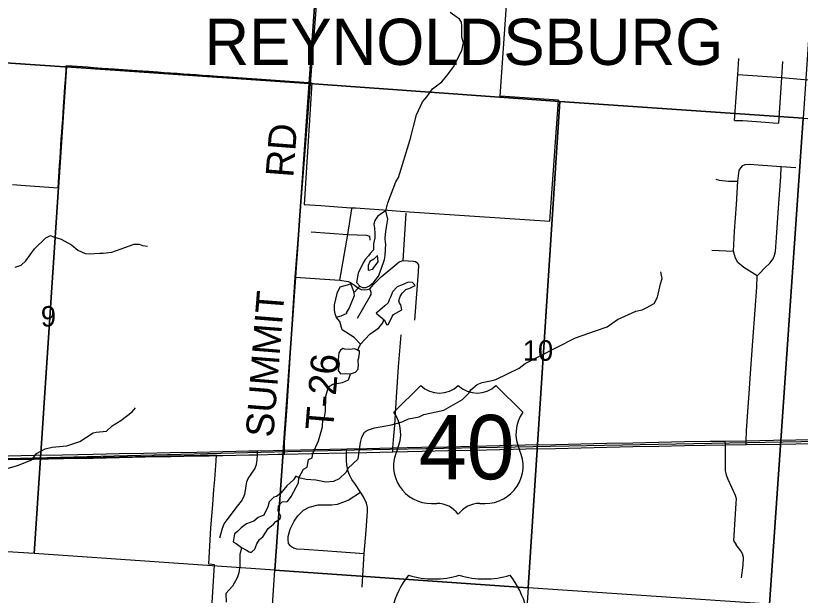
# Model space of a CAD drawing. Extents: x 0 to 34, y 0 to 22.
# Drawn here: x 4.853 to 6.46, y 19.099 to 20.286 of the extents above; entities that cross this region are included whole.
import ezdxf

# ---------------------------------------------------------------- set-up
doc = ezdxf.new("R2010")
doc.units = 0
for name, color, linetype in [('GM_X_Corporation', 7, 'Continuous'), ('GM_X_Corporation_Text', 7, 'Continuous'), ('GM_X_Interstate_Shield', 7, 'Continuous'), ('GM_X_Minor_Lake', 7, 'Continuous'), ('GM_X_Minor_River', 7, 'Continuous'), ('GM_X_Rail_Line', 7, 'Continuous'), ('GM_X_Section_Text', 7, 'Continuous'), ('GM_X_Township_Road', 7, 'Continuous'), ('GM_X_Township_Road_Text', 7, 'Continuous'), ('GM_X_US_Location', 7, 'Continuous'), ('GM_X_US_Route', 7, 'Continuous'), ('GM_X_US_Shield', 7, 'Continuous')]:
    doc.layers.add(name, color=color, linetype=linetype)

msp = doc.modelspace()

# ---------------------------------------------------------------- linework, layer by layer
at = {"layer": 'GM_X_Corporation'}
for points in [[(4.4912, 20.7461), (4.8271, 20.7263), (5.3592, 20.6938), (5.4919, 20.6855), (5.4537, 20.1473), (4.9568, 20.181), (4.9537, 20.1812), (4.4572, 20.2143)], [(5.4919, 20.6855), (5.8824, 20.6656), (6.3999, 20.6351), (6.5029, 20.629), (6.4654, 20.076), (5.9674, 20.1102), (5.4537, 20.1473)], [(4.4572, 20.2143), (4.9537, 20.1812), (4.9568, 20.181), (4.8908, 19.1842), (4.3886, 19.2156)], [(4.9568, 20.181), (5.4537, 20.1473), (5.3836, 19.1504), (4.8908, 19.1842)], [(5.4537, 20.1473), (5.9674, 20.1102), (5.9022, 19.114), (5.3836, 19.1504)], [(5.9674, 20.1102), (6.4654, 20.076), (6.3967, 19.0805), (5.9022, 19.114)], [(6.4654, 20.076), (6.9844, 20.0383), (6.914, 19.0437), (6.3967, 19.0805)], [(5.3836, 19.1504), (5.9022, 19.114), (5.8356, 18.116), (5.3174, 18.1535)]]:
    msp.add_lwpolyline(points, close=True, dxfattribs=at)
for points in [[(4.8462, 19.9402), (4.8724, 19.9383), (4.8824, 19.9376), (4.9399, 19.9335), (4.9427, 19.9787), (4.9438, 19.9938), (4.9447, 20.0075), (4.9456, 20.0201), (4.9465, 20.0336), (4.9474, 20.0467), (4.9483, 20.0599), (4.9493, 20.0734), (4.9502, 20.0864), (4.9511, 20.1), (4.9523, 20.1177), (4.9539, 20.1402), (4.9549, 20.1545), (4.9569, 20.1838), (4.9689, 20.1829), (4.9998, 20.1808), (5.0132, 20.1799), (5.0304, 20.1787), (5.0547, 20.1769), (5.0817, 20.1752), (5.1017, 20.1738), (5.1259, 20.172), (5.1438, 20.1708), (5.1572, 20.1698), (5.1703, 20.1689), (5.1835, 20.1679), (5.1969, 20.167), (5.2103, 20.166), (5.2227, 20.1651), (5.2359, 20.1642), (5.2497, 20.1632), (5.2662, 20.162), (5.2897, 20.1604), (5.3079, 20.1591), (5.4529, 20.1488), (5.4597, 20.1483), (5.4437, 19.8991), (5.4777, 19.8968), (5.5393, 19.8924), (5.5488, 19.892), (5.606, 19.8881), (5.6501, 19.8851), (5.6596, 19.8841), (5.6901, 19.8824), (5.947, 19.865), (5.9645, 20.1129), (5.8451, 20.1209), (5.864, 20.3961)], [(5.2534, 19.0508), (5.2599, 19.1614), (5.2484, 19.1624), (5.2529, 19.2371), (5.2566, 19.2849), (5.259, 19.3154), (5.2606, 19.3362), (5.2636, 19.3742), (5.2645, 19.3856), (4.966, 19.3796), (4.9014, 19.3783), (4.8704, 19.3777), (4.8144, 19.3765)]]:
    msp.add_lwpolyline(points, dxfattribs=at)
at = {"layer": 'GM_X_Interstate_Shield'}
for centre, start, end in [((5.797, 19.0298), 141.669, 165.8066), ((5.7096, 19.3098), 253.0091, 286.9909), ((5.8134, 19.3098), 253.0091, 286.9909), ((5.726, 19.0298), 14.1934, 38.331)]:
    msp.add_arc(centre, 0.1776, start, end, dxfattribs=at)
at = {"layer": 'GM_X_Minor_Lake'}
for points in [[(5.6112, 19.8862), (5.6021, 19.8806), (5.5937, 19.8749), (5.5884, 19.8662), (5.5865, 19.8586), (5.588, 19.851), (5.5888, 19.84), (5.5884, 19.8312), (5.5861, 19.8183), (5.5857, 19.8142), (5.5857, 19.8073), (5.5857, 19.8066), (5.5792, 19.799), (5.5754, 19.7941), (5.5686, 19.7865), (5.5644, 19.7797), (5.5541, 19.7588), (5.5511, 19.7395), (5.5575, 19.7322)], [(5.5575, 19.7322), (5.5632, 19.7292), (5.5707, 19.7292), (5.5779, 19.7326), (5.5867, 19.7402), (5.5962, 19.7523), (5.6015, 19.7667), (5.608, 19.7864), (5.6095, 19.7948), (5.6107, 19.8187), (5.6103, 19.8198), (5.6099, 19.8312), (5.6107, 19.8441), (5.613, 19.857), (5.6149, 19.8691), (5.6112, 19.8862)], [(5.5943, 19.7944), (5.5864, 19.7872), (5.578, 19.7823), (5.575, 19.7743), (5.575, 19.7649)], [(5.5841, 19.7667), (5.5867, 19.7698), (5.5867, 19.7701), (5.5955, 19.7815), (5.5943, 19.7944)], [(5.575, 19.7649), (5.5841, 19.7667)], [(5.5396, 19.7368), (5.5317, 19.7338), (5.5169, 19.7296), (5.5108, 19.7171), (5.5055, 19.6939), (5.5051, 19.6826), (5.5066, 19.6761), (5.5092, 19.6681), (5.5198, 19.6712)], [(5.5198, 19.6712), (5.5316, 19.6765), (5.5308, 19.6772), (5.5361, 19.6863), (5.5403, 19.6966), (5.5437, 19.7045), (5.5471, 19.7129), (5.5453, 19.7212), (5.5396, 19.7368)], [(5.6441, 19.6835), (5.6415, 19.6937), (5.6392, 19.6971), (5.6377, 19.7017), (5.6404, 19.7108), (5.6442, 19.7173), (5.6518, 19.7252), (5.6605, 19.7278), (5.6673, 19.7312), (5.6711, 19.7335), (5.6658, 19.7396), (5.6571, 19.7404), (5.6476, 19.7358), (5.634, 19.7302), (5.6249, 19.72), (5.6214, 19.7109), (5.618, 19.704), (5.6161, 19.698), (5.6089, 19.6919), (5.5987, 19.6828), (5.5915, 19.6768), (5.6077, 19.6627)], [(5.6077, 19.6627), (5.613, 19.6524), (5.616, 19.6532), (5.6198, 19.6611), (5.624, 19.6695), (5.6267, 19.674), (5.6377, 19.6797), (5.6441, 19.6835)], [(5.5545, 19.577), (5.5545, 19.5808), (5.5557, 19.585), (5.5568, 19.5948), (5.5568, 19.5986), (5.5474, 19.6032), (5.5364, 19.6025), (5.5273, 19.6028), (5.5232, 19.604), (5.5179, 19.6006), (5.5148, 19.5956), (5.5137, 19.582), (5.5152, 19.5736), (5.5137, 19.5592), (5.5182, 19.5524), (5.5292, 19.5531), (5.539, 19.5524)], [(5.539, 19.5524), (5.5488, 19.5554), (5.5541, 19.5622), (5.5545, 19.5641), (5.5549, 19.5713), (5.5545, 19.577)], [(5.4328, 19.3392), (5.4309, 19.3404), (5.4267, 19.3426), (5.4218, 19.3354), (5.4082, 19.3229), (5.3957, 19.3078), (5.387, 19.3013), (5.382, 19.2998), (5.3718, 19.2903), (5.3691, 19.2797), (5.3612, 19.2626), (5.3494, 19.2581), (5.3404, 19.2505), (5.326, 19.2452), (5.3146, 19.2369), (5.3074, 19.2297), (5.301, 19.2244), (5.2987, 19.2081), (5.3044, 19.2046), (5.3157, 19.1967)], [(5.3157, 19.1967), (5.3259, 19.1913), (5.3312, 19.1879), (5.3335, 19.1868), (5.3361, 19.1871), (5.3429, 19.1932), (5.3467, 19.2042), (5.352, 19.2133), (5.3592, 19.2182), (5.3702, 19.2353), (5.3808, 19.2444), (5.3858, 19.2501), (5.3941, 19.2546), (5.396, 19.2607), (5.3903, 19.2713), (5.3915, 19.2823), (5.3987, 19.2899), (5.4096, 19.291), (5.4172, 19.3013), (5.432, 19.3293), (5.4328, 19.3392)]]:
    msp.add_lwpolyline(points, dxfattribs=at)
at = {"layer": 'GM_X_Minor_River'}
for points in [[(5.6112, 19.8862), (5.615, 19.9025), (5.6318, 19.9454), (5.6367, 19.9545), (5.6607, 20.0326), (5.6741, 20.0831), (5.6859, 20.1096), (5.695, 20.1195), (5.7067, 20.1358), (5.7257, 20.1502), (5.7379, 20.1653), (5.7496, 20.1808), (5.7667, 20.2146), (5.7698, 20.2301), (5.7664, 20.2419), (5.7668, 20.2647), (5.7657, 20.2723), (5.7619, 20.2784), (5.743, 20.2925)], [(4.8522, 19.7706), (4.864, 19.7748), (4.8738, 19.7839), (4.8916, 19.8085), (4.9147, 19.8309), (4.9242, 19.8354), (4.9302, 19.8331), (4.9461, 19.8278), (4.9673, 19.8168), (4.9801, 19.8058), (4.9953, 19.7989), (5.0043, 19.7978), (5.0252, 19.7993), (5.032, 19.7992), (5.0498, 19.8015), (5.0955, 19.8178), (5.1061, 19.8181), (5.1126, 19.8151), (5.1228, 19.8139)], [(5.5541, 19.3781), (5.5591, 19.4119), (5.5622, 19.4225), (5.5671, 19.4327), (5.5735, 19.4369), (5.5879, 19.4418), (5.6224, 19.4482), (5.6448, 19.4538), (5.6577, 19.4599), (5.6793, 19.4644), (5.6887, 19.4689), (5.73, 19.4779), (5.7679, 19.4995), (5.7812, 19.5124), (5.785, 19.5196), (5.7983, 19.5302), (5.8085, 19.5343), (5.8286, 19.5384), (5.8362, 19.5407), (5.8843, 19.5641), (5.8961, 19.5732), (5.9245, 19.5879), (5.9996, 19.6261), (6.0405, 19.6404), (6.064, 19.6484), (6.0852, 19.6639), (6.1227, 19.6805), (6.136, 19.6835), (6.1443, 19.6877), (6.1606, 19.6964), (6.1675, 19.7092), (6.1732, 19.7366), (6.177, 19.7476), (6.1744, 19.7612)], [(5.5575, 19.7322), (5.5472, 19.7197)], [(5.5591, 19.6134), (5.5463, 19.6264), (5.5213, 19.6427), (5.5168, 19.6598), (5.5092, 19.6681)], [(5.5568, 19.5986), (5.5538, 19.6017), (5.5591, 19.6134), (5.5785, 19.6335), (5.5967, 19.6464), (5.605, 19.657), (5.6066, 19.6631)], [(5.4328, 19.3392), (5.4426, 19.357), (5.4498, 19.3612), (5.4525, 19.3768), (5.4601, 19.3805), (5.4612, 19.3893), (5.473, 19.4151), (5.481, 19.4435), (5.4817, 19.4587), (5.4855, 19.4636), (5.4874, 19.4761), (5.4882, 19.5069), (5.4936, 19.5259), (5.5026, 19.5312), (5.5223, 19.5349), (5.5348, 19.5402), (5.539, 19.5524)], [(4.8188, 19.3536), (4.857, 19.3646), (4.8861, 19.3759), (4.8956, 19.3892), (4.9134, 19.3987), (4.9278, 19.4024), (4.9581, 19.4051), (4.9846, 19.4134), (5.0114, 19.4316), (5.0175, 19.4331), (5.0387, 19.4349), (5.0508, 19.4456), (5.0682, 19.4565), (5.0917, 19.4743), (5.0981, 19.4827)], [(5.5541, 19.3781), (5.5331, 19.3581), (5.5297, 19.3512), (5.5156, 19.3376), (5.5039, 19.3315), (5.4884, 19.3304), (5.468, 19.3346), (5.4479, 19.3358), (5.4328, 19.3392)], [(5.3157, 19.1967), (5.3119, 19.1826), (5.3119, 19.1587), (5.3103, 19.1447), (5.3065, 19.1348), (5.2971, 19.1177), (5.2834, 19.1026), (5.2838, 19.0844)]]:
    msp.add_lwpolyline(points, dxfattribs=at)
at = {"layer": 'GM_X_Rail_Line'}
msp.add_lwpolyline([(3.8879, 19.3555), (4.0965, 19.3606), (5.5472, 19.3964), (6.4975, 19.4141), (6.7591, 19.4199), (8.4183, 19.4472), (8.6503, 19.4472), (8.9, 19.451)], dxfattribs=at)
at = {"layer": 'GM_X_Township_Road'}
for p, q in [((5.6463, 19.7842), (5.6527, 19.8811)), ((6.2784, 19.8057), (6.3231, 19.8036))]:
    msp.add_line(p, q, dxfattribs=at)
for points in [[(5.4565, 20.146), (5.4788, 20.4326), (5.4959, 20.6894)], [(6.3249, 20.0714), (6.3316, 20.1653), (6.334, 20.1982)], [(6.4157, 20.0656), (6.422, 20.1592), (6.4241, 20.1919)], [(6.3316, 20.1653), (6.422, 20.1592), (6.4605, 20.1557), (6.4761, 20.1545)], [(5.4032, 19.3879), (5.4032, 19.396), (5.4034, 19.4121), (5.4087, 19.4844), (5.4136, 19.5619), (5.4178, 19.6325), (5.4227, 19.7087), (5.4257, 19.7506), (5.4565, 20.146)], [(6.3249, 20.0714), (6.3424, 20.071), (6.3888, 20.0677), (6.4044, 20.0666), (6.4157, 20.0656)], [(6.3715, 19.7528), (6.344, 19.7699), (6.3318, 19.7805), (6.327, 19.7891), (6.3248, 19.796), (6.3231, 19.8036), (6.325, 19.8442), (6.329, 19.8992), (6.3321, 19.9466), (6.3348, 19.9687), (6.3377, 19.9742), (6.342, 19.9787), (6.3472, 19.9811), (6.3566, 19.9819), (6.3732, 19.9804)], [(6.349, 19.4075), (6.3489, 19.4154), (6.3494, 19.4353), (6.3524, 19.4751), (6.3549, 19.5122), (6.3576, 19.5533), (6.3626, 19.6194), (6.3673, 19.6832), (6.3706, 19.7297), (6.3715, 19.7528), (6.3764, 19.7579), (6.3872, 19.7696), (6.3977, 19.7792), (6.404, 19.7878), (6.407, 19.7955), (6.4089, 19.8031), (6.4111, 19.8318), (6.4153, 19.8925), (6.4196, 19.9561), (6.4205, 19.9769)], [(6.3732, 19.9804), (6.4205, 19.9769), (6.4508, 19.9747)], [(6.2865, 19.951), (6.2936, 19.9492), (6.313, 19.9471), (6.3321, 19.9466)], [(5.517, 19.7443), (5.5333, 19.8376), (5.5414, 19.8903)], [(5.4582, 19.8431), (5.5333, 19.8376), (5.5713, 19.836), (5.5774, 19.8345), (5.5784, 19.8259)], [(5.4257, 19.7506), (5.517, 19.7443), (5.534, 19.7416), (5.5389, 19.7394), (5.547, 19.7339), (5.5528, 19.7292), (5.5567, 19.7269), (5.5603, 19.7253), (5.568, 19.7247), (5.573, 19.7253), (5.5783, 19.7266), (5.5857, 19.7353), (5.6015, 19.751), (5.6333, 19.7779), (5.6386, 19.782), (5.6463, 19.7842), (5.6668, 19.7834), (5.6721, 19.7823), (5.6768, 19.7787)], [(5.6701, 19.6622), (5.6776, 19.761), (5.6784, 19.774), (5.6768, 19.7787)], [(5.5531, 19.6663), (5.5788, 19.7117), (5.5807, 19.7151), (5.5807, 19.7189), (5.5783, 19.7266)], [(5.6257, 19.3927), (5.6256, 19.4008), (5.6265, 19.4169), (5.6296, 19.4473), (5.6332, 19.5042), (5.637, 19.5666), (5.6425, 19.6321)], [(6.3055, 19.4147), (6.3056, 19.4069), (6.3058, 19.3699), (6.3062, 19.3538), (6.307, 19.3483), (6.3088, 19.3431), (6.3116, 19.3364), (6.3267, 19.3036), (6.3282, 19.2968), (6.328, 19.2866), (6.3229, 19.2111), (6.3286, 19.2023)], [(5.2711, 19.2167), (5.2767, 19.2361), (5.2803, 19.2448), (5.286, 19.2533), (5.3075, 19.2811), (5.3153, 19.2916), (5.3196, 19.2992), (5.3222, 19.3062), (5.3237, 19.3135), (5.3248, 19.3232), (5.3265, 19.3309), (5.3291, 19.3378), (5.3341, 19.3451), (5.3429, 19.3578), (5.3461, 19.3663), (5.3478, 19.376), (5.3483, 19.3866), (5.3483, 19.3947)], [(5.5626, 19.1153), (5.5667, 19.1843), (5.5705, 19.2313), (5.5734, 19.2701), (5.5736, 19.2786), (5.5716, 19.2875), (5.5652, 19.3003), (5.5591, 19.3101), (5.5486, 19.326), (5.5417, 19.336), (5.5367, 19.3456), (5.534, 19.3526), (5.5312, 19.3658), (5.5303, 19.3744), (5.5307, 19.3908), (5.5311, 19.3987)], [(5.4155, 19.2003), (5.4114, 19.205), (5.4109, 19.2129), (5.4112, 19.219), (5.4152, 19.2342), (5.4234, 19.2506), (5.431, 19.2618), (5.4424, 19.2733), (5.4538, 19.2794), (5.4723, 19.2839), (5.4855, 19.2843), (5.5007, 19.2839), (5.5123, 19.2855), (5.5337, 19.2935), (5.5591, 19.3101)], [(6.3397, 19.1348), (6.3427, 19.1607), (6.3433, 19.1762), (6.3416, 19.1838), (6.3381, 19.1897), (6.3286, 19.2023)], [(5.4155, 19.2003), (5.4217, 19.1959), (5.4278, 19.1936), (5.4438, 19.193), (5.4824, 19.1904), (5.5667, 19.1843)]]:
    msp.add_lwpolyline(points, dxfattribs=at)
at = {"layer": 'GM_X_US_Route'}
msp.add_line((5.2491, 19.3846), (5.2611, 19.3848), dxfattribs=at)
for points in [[(5.2611, 19.3848), (5.2771, 19.3851), (5.3303, 19.3863), (5.3483, 19.3866), (5.3899, 19.3876), (5.4032, 19.3879), (5.4586, 19.3892), (5.5307, 19.3908), (5.5718, 19.3915), (5.6257, 19.3927), (5.6857, 19.3941), (5.7381, 19.3951), (5.7914, 19.3963), (5.8439, 19.3975), (5.8975, 19.3987), (5.9582, 19.3997), (6.0112, 19.401), (6.0639, 19.4023), (6.1168, 19.4034), (6.1699, 19.4045), (6.2229, 19.4054), (6.3056, 19.4069), (6.349, 19.4075), (6.4204, 19.4086), (6.5111, 19.4101)], [(5.3483, 19.3947), (5.3801, 19.3955), (5.4032, 19.396), (5.4362, 19.3966), (5.4631, 19.3973), (5.5311, 19.3987), (5.5718, 19.3996), (5.6256, 19.4008), (5.684, 19.402), (5.7369, 19.4031), (5.7903, 19.4043), (5.8436, 19.4054), (5.8967, 19.4067), (5.9583, 19.4078), (6.0104, 19.409), (6.0633, 19.4102), (6.1166, 19.4113), (6.1697, 19.4124), (6.2224, 19.4134), (6.275, 19.4142), (6.3055, 19.4147), (6.3489, 19.4154), (6.4049, 19.4163), (6.4506, 19.417), (6.5109, 19.4181)], [(4.4049, 19.3759), (4.4337, 19.3764), (4.4614, 19.377), (4.5194, 19.3783), (4.5726, 19.3794), (4.6246, 19.3806), (4.678, 19.3816), (4.7315, 19.3826), (4.7845, 19.3837), (4.8384, 19.3845), (4.8903, 19.3857), (4.9487, 19.3866), (5.0115, 19.388), (5.0646, 19.389), (5.1152, 19.3899), (5.1697, 19.391), (5.224, 19.3922), (5.277, 19.3932), (5.3303, 19.3944), (5.3483, 19.3947)], [(4.5926, 19.3717), (4.6246, 19.3724), (4.678, 19.3735), (4.7315, 19.3745), (4.7846, 19.3756), (4.8378, 19.3768), (4.8904, 19.3776), (4.9507, 19.3788), (5.0115, 19.3799), (5.0646, 19.3809), (5.1182, 19.3822), (5.1708, 19.3832), (5.224, 19.3841), (5.2491, 19.3846)]]:
    msp.add_lwpolyline(points, dxfattribs=at)
at = {"layer": 'GM_X_US_Shield'}
for p, q in [((5.6825, 19.5285), (5.6276, 19.4736)), ((5.8913, 19.4736), (5.8364, 19.5285)), ((5.7045, 19.2868), (5.7155, 19.2868)), ((5.8034, 19.2868), (5.8144, 19.2868))]:
    msp.add_line(p, q, dxfattribs=at)
for centre, radius, start, end in [((5.721, 19.5677), 0.0549, 225.573, 314.427), ((5.7979, 19.5677), 0.0549, 225.573, 314.427), ((5.5646, 19.4295), 0.0769, 334.5471, 35.0009), ((5.9543, 19.4295), 0.0769, 144.9991, 205.4529), ((5.7037, 19.3637), 0.0769, 154.8319, 270.6383), ((5.8152, 19.3637), 0.0769, 269.3617, 25.1681), ((5.7155, 19.2319), 0.0549, 36.8699, 90), ((5.8034, 19.2319), 0.0549, 90, 143.1301)]:
    msp.add_arc(centre, radius, start, end, dxfattribs=at)

# ---------------------------------------------------------------- texts
at = {"layer": 'GM_X_Corporation_Text'}
msp.add_text('REYNOLDSBURG', height=0.094697, rotation=0, dxfattribs=at).set_placement((5.2396, 20.185))
at = {"layer": 'GM_X_Section_Text'}
for s, height, p in [('9', 0.0419, (4.9045, 19.6492)), ('10', 0.04186, (5.8915, 19.5792))]:
    msp.add_text(s, height=height, rotation=0, dxfattribs=at).set_placement(p)
at = {"layer": 'GM_X_Township_Road_Text'}
for s, rotation, p in [('RD', 85.5641, (5.4213, 19.9534)), ('SUMMIT', 85.5226, (5.3805, 19.4209)), ('T-26', 85.3834, (5.5028, 19.4354))]:
    msp.add_text(s, height=0.05682, rotation=rotation, dxfattribs=at).set_placement(p)
at = {"layer": 'GM_X_US_Location'}
for s in ['0', '/']:
    msp.add_text(s, height=0.000189, dxfattribs=at).set_placement((5.7594, 19.4011))
msp.add_text('40', height=0.000189, rotation=0, dxfattribs=at).set_placement((5.7203, 19.3619))
at = {"layer": 'GM_X_US_Shield'}
msp.add_text('40', height=0.13184, dxfattribs=at).set_placement((5.6786, 19.3363))

doc.saveas('drawing.dxf')
